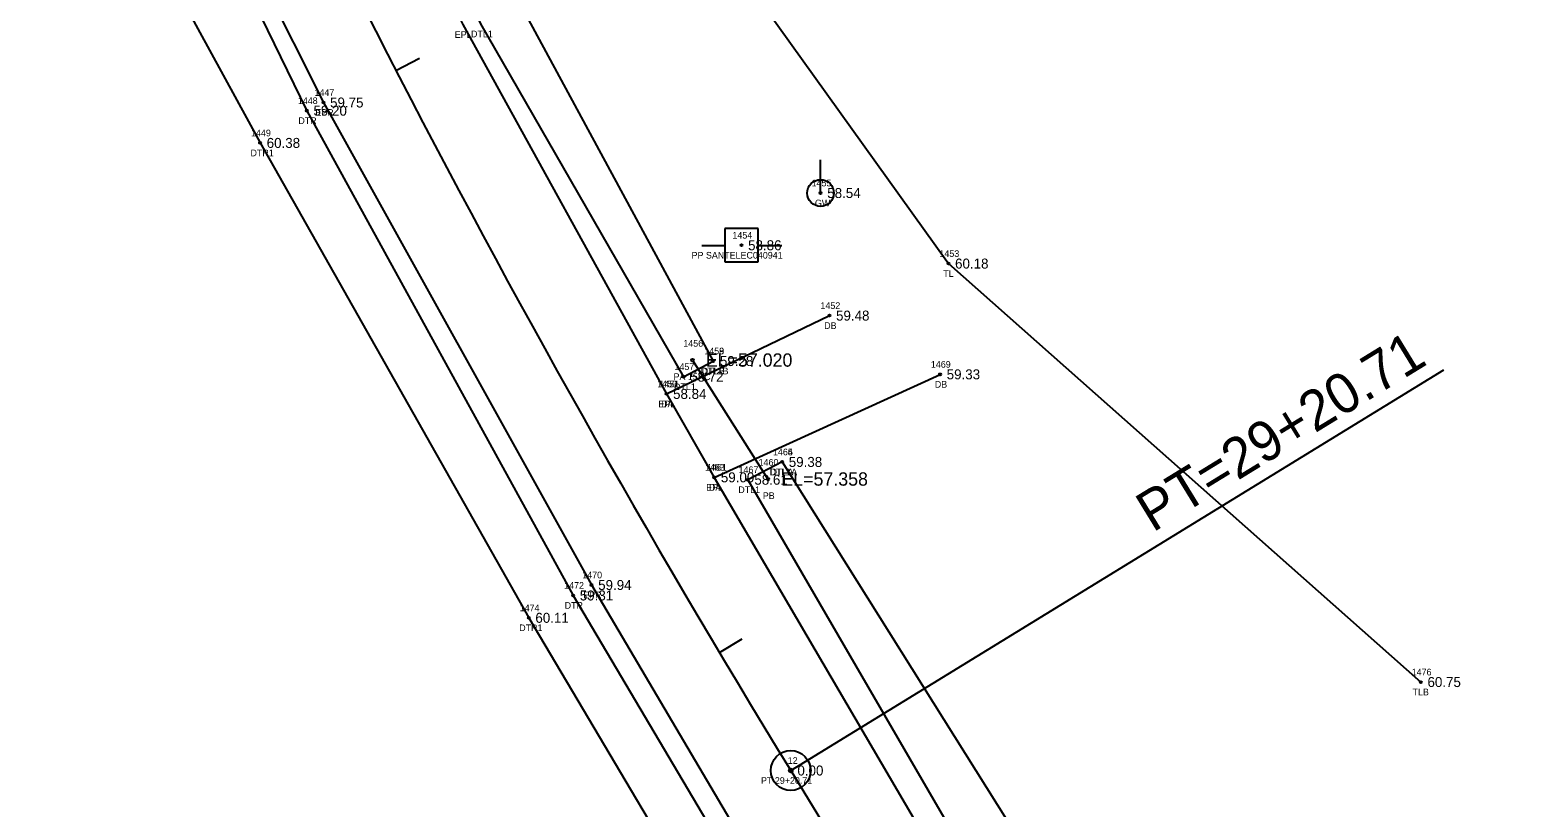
# Model space of a CAD drawing. Extents: x 2396531 to 2397633, y 770203 to 772837.
# Drawn here: x 2397143 to 2397369.4, y 770887 to 771003.7 of the extents above; entities that cross this region are included whole.
import ezdxf

# ---------------------------------------------------------------- set-up
doc = ezdxf.new("R2010")
doc.units = 0
for name, color, linetype in [('RD_EX_DR_Pipe', 7, 'Continuous'), ('RD_EX_DR_Pipe_txCode', 7, 'Continuous'), ('RD_EX_Driveway', 7, 'Continuous'), ('RD_EX_Driveway_txCode', 7, 'Continuous'), ('RD_EX_H2O', 7, 'Continuous'), ('RD_EX_H2O_txCode', 7, 'Continuous'), ('RD_EX_Road', 7, 'Continuous'), ('RD_EX_Road_txCode', 7, 'Continuous'), ('RD_EX_TX_Driveway_ELEV', 7, 'Continuous'), ('RD_EX_TX_H2O_ELEV', 7, 'Continuous'), ('RD_EX_TX_Road_ELEV', 7, 'Continuous'), ('RD_EX_TX_UT_ELEV', 7, 'Continuous'), ('RD_EX_TX_VEG_ELEV', 7, 'Continuous'), ('RD_EX_UT', 7, 'Continuous'), ('RD_EX_UT_txCode', 7, 'Continuous'), ('RD_EX_VEG', 7, 'Continuous'), ('RD_EX_VEG_txCode', 7, 'Continuous'), ('RD_HC_Cl', 7, 'Continuous'), ('RD_HC_Data', 7, 'Continuous'), ('RD_HC_Data_Tic', 7, 'Continuous'), ('RD_HC_Survey_ELEV', 7, 'Continuous'), ('RD_HC_txCode', 7, 'Continuous'), ('RD_SMD_Locator', 7, 'Continuous'), ('RD_TX_Pipe_ElevEX', 7, 'Continuous')]:
    doc.layers.add(name, color=color, linetype=linetype)

msp = doc.modelspace()

# ---------------------------------------------------------------- linework, layer by layer
at = {"layer": 'RD_EX_DR_Pipe'}
msp.add_line((2397242.45, 770954.2), (2397253.8, 770936.34), dxfattribs=at)
at = {"layer": 'RD_EX_Driveway'}
for p, q in [((2397238.54, 770949.11), (2397263.02, 770960.87)), ((2397245.72, 770936.59), (2397279.64, 770952.05))]:
    msp.add_line(p, q, dxfattribs=at)
at = {"layer": 'RD_EX_H2O'}
msp.add_line((2397255.92, 770938.9), (2397291.42, 770882.36), dxfattribs=at)
for points in [[(2397108.85, 771101.86), (2397130.27, 771108.67), (2397157.99, 771046.03), (2397184.53, 770991.63), (2397224.53, 770918.86), (2397257.48, 770863.23)], [(2397108.85, 771101.86), (2397123.52, 771093.58), (2397147.97, 771040.86), (2397177.5, 770986.79), (2397217.86, 770915.5), (2397251.15, 770859.33)], [(2397186.58, 771067.61), (2397181.36, 771063.96), (2397210.6, 771004.65), (2397241.1, 770951.7), (2397245.58, 770954.05)], [(2397186.58, 771067.61), (2397189.06, 771064.15), (2397217.13, 771006.57), (2397245.58, 770954.05)], [(2397255.92, 770938.9), (2397250.75, 770936.23), (2397284.14, 770878.8)]]:
    msp.add_lwpolyline(points, dxfattribs=at)
at = {"layer": 'RD_EX_Road'}
for points in [[(2397113.76, 771228.75), (2397130.87, 771177.98), (2397154.19, 771118.49), (2397170.38, 771081.25), (2397178.53, 771063.49), (2397207.96, 771004.56), (2397238.54, 770949.11), (2397245.72, 770936.59), (2397280.76, 770876.73)], [(2397093.16, 771212.62), (2397108.35, 771171.65), (2397122.66, 771133.29), (2397131.66, 771109.5), (2397159.86, 771046.96), (2397187.02, 770992.86), (2397227.29, 770920.43), (2397260.16, 770864.73)]]:
    msp.add_lwpolyline(points, dxfattribs=at)
at = {"layer": 'RD_EX_UT'}
for p, q in [((2397261.7, 770979.27), (2397261.7, 770984.27)), ((2397252.3, 770973.93), (2397247.3, 770973.93)), ((2397247.3, 770973.93), (2397247.3, 770968.93)), ((2397252.3, 770968.93), (2397252.3, 770973.93)), ((2397243.87, 770971.37), (2397247.33, 770971.37)), ((2397252.22, 770971.37), (2397255.87, 770971.37)), ((2397247.3, 770968.93), (2397252.3, 770968.93))]:
    msp.add_line(p, q, dxfattribs=at)
msp.add_circle((2397261.7, 770979.27), 2, dxfattribs=at)
at = {"layer": 'RD_EX_VEG'}
msp.add_lwpolyline([(2397258.88, 771057.27), (2397220.63, 771052.76), (2397280.9, 770968.68), (2397351.86, 770905.86)], dxfattribs=at)
at = {"layer": 'RD_HC_Cl'}
msp.add_line((2397257.22, 770892.58), (2397369.44, 770709.51), dxfattribs=at)
msp.add_arc((2398682.18, 771766.08), 1671.39, 194.59125, 211.50817, dxfattribs=at)
at = {"layer": 'RD_HC_Data'}
msp.add_line((2397257.22, 770892.58), (2397355.33, 770952.72), dxfattribs=at)
for radius in [3, 0.282]:
    msp.add_circle((2397257.22, 770892.58), radius, dxfattribs=at)
at = {"layer": 'RD_HC_Data_Tic'}
for p, q in [((2397197.9, 770997.67), (2397201.45, 770999.51)), ((2397246.5, 770910.3), (2397249.94, 770912.34))]:
    msp.add_line(p, q, dxfattribs=at)
at = {"layer": 'RD_SMD_Locator'}
for centre, radius in [((2397187.02, 770992.86), 0.15), ((2397184.53, 770991.63), 0.15), ((2397177.5, 770986.79), 0.15), ((2397261.7, 770979.27), 0.15), ((2397249.81, 770971.43), 0.15), ((2397280.9, 770968.68), 0.15), ((2397263.02, 770960.87), 0.15), ((2397242.45, 770954.2), 0.2), ((2397245.58, 770954.05), 0.15), ((2397245.58, 770954.05), 0.15), ((2397279.64, 770952.05), 0.15), ((2397241.1, 770951.7), 0.15), ((2397238.54, 770949.11), 0.15), ((2397238.54, 770949.11), 0.15), ((2397255.92, 770938.9), 0.15), ((2397255.92, 770938.9), 0.15), ((2397245.72, 770936.59), 0.15), ((2397245.72, 770936.59), 0.15), ((2397250.75, 770936.23), 0.15), ((2397253.8, 770936.34), 0.2), ((2397227.29, 770920.43), 0.15), ((2397224.53, 770918.86), 0.15), ((2397217.86, 770915.5), 0.15), ((2397351.86, 770905.86), 0.15), ((2397257.22, 770892.58), 0.15)]:
    msp.add_circle(centre, radius, dxfattribs=at)

# ---------------------------------------------------------------- texts
at = {"layer": 'RD_EX_DR_Pipe_txCode'}
for s, p in [('1456', (2397241.08, 770956.2)), ('PA 15RC', (2397239.61, 770951.2)), ('1460', (2397252.39, 770938.34)), ('PB', (2397253.02, 770933.34))]:
    msp.add_text(s, height=1, dxfattribs=at).set_placement(p)
at = {"layer": 'RD_EX_Driveway_txCode'}
for s, p in [('1452', (2397261.68, 770961.87)), ('DB', (2397262.24, 770958.87)), ('1469', (2397278.27, 770953.05)), ('1451', (2397237.48, 770950.11)), ('DB', (2397278.86, 770950.05)), ('DA', (2397237.75, 770947.11)), ('1463', (2397244.35, 770937.59)), ('DA', (2397244.93, 770934.59))]:
    msp.add_text(s, height=1, dxfattribs=at).set_placement(p)
at = {"layer": 'RD_EX_H2O_txCode'}
for s, p in [('DTL1', (2397209.19, 771002.65)), ('1448', (2397183.18, 770992.63)), ('DTR', (2397183.26, 770989.63)), ('1449', (2397176.15, 770987.79)), ('DTR1', (2397176.07, 770984.79)), ('1458', (2397244.23, 770955.05)), ('1459', (2397244.23, 770955.05)), ('1457', (2397239.75, 770952.7)), ('DTL1B', (2397243.7, 770952.05)), ('DTLB', (2397243.86, 770952.05)), ('DTL1', (2397239.69, 770949.7)), ('1464', (2397254.55, 770939.9)), ('1465', (2397254.55, 770939.9)), ('1467', (2397249.38, 770937.23)), ('DTL1A', (2397254.02, 770936.9)), ('DTLA', (2397254.19, 770936.9)), ('DTL1', (2397249.34, 770934.23)), ('1472', (2397223.18, 770919.86)), ('1474', (2397216.51, 770916.5)), ('DTR', (2397223.26, 770916.86)), ('DTR1', (2397216.43, 770913.5))]:
    msp.add_text(s, height=1, dxfattribs=at).set_placement(p)
at = {"layer": 'RD_EX_Road_txCode'}
for s, p in [('EPL', (2397206.75, 771002.56)), ('1447', (2397185.68, 770993.86)), ('EPR', (2397185.8, 770990.86)), ('1450', (2397237.16, 770950.11)), ('EPL', (2397237.34, 770947.11)), ('1461', (2397244.64, 770937.59)), ('EPL', (2397244.52, 770934.59)), ('1470', (2397225.9, 770921.43)), ('EPR', (2397226.06, 770918.43))]:
    msp.add_text(s, height=1, dxfattribs=at).set_placement(p)
at = {"layer": 'RD_EX_TX_Driveway_ELEV'}
for s, p in [('59.48', (2397264.02, 770960.12)), ('59.33', (2397280.64, 770951.3)), ('58.84', (2397239.54, 770948.36)), ('59.00', (2397246.72, 770935.84))]:
    msp.add_text(s, height=1.5, dxfattribs=at).set_placement(p)
at = {"layer": 'RD_EX_TX_H2O_ELEV'}
for s, p in [('59.20', (2397185.53, 770990.88)), ('60.38', (2397178.5, 770986.04)), ('59.28', (2397246.58, 770953.3)), ('59.28', (2397246.58, 770953.3)), ('58.72', (2397242.1, 770950.95)), ('59.38', (2397256.92, 770938.15)), ('59.38', (2397256.92, 770938.15)), ('58.61', (2397251.75, 770935.48)), ('59.31', (2397225.53, 770918.11)), ('60.11', (2397218.86, 770914.75))]:
    msp.add_text(s, height=1.5, dxfattribs=at).set_placement(p)
at = {"layer": 'RD_EX_TX_Road_ELEV'}
for s, p in [('59.75', (2397188.02, 770992.11)), ('58.84', (2397239.54, 770948.36)), ('59.00', (2397246.72, 770935.84)), ('59.94', (2397228.29, 770919.68))]:
    msp.add_text(s, height=1.5, dxfattribs=at).set_placement(p)
at = {"layer": 'RD_EX_TX_UT_ELEV'}
msp.add_text('58.54', height=1.5, dxfattribs=at).set_placement((2397262.7, 770978.52))
at = {"layer": 'RD_EX_TX_VEG_ELEV'}
for s, p in [('60.18', (2397281.9, 770967.93)), ('60.75', (2397352.86, 770905.11))]:
    msp.add_text(s, height=1.5, dxfattribs=at).set_placement(p)
at = {"layer": 'RD_EX_UT_txCode'}
for s, p in [('1455', (2397260.35, 770980.27)), ('GW', (2397260.85, 770977.27)), ('1454', (2397248.46, 770972.43)), ('PP SANTELEC040941', (2397242.32, 770969.43))]:
    msp.add_text(s, height=1, dxfattribs=at).set_placement(p)
at = {"layer": 'RD_EX_VEG_txCode'}
for s, p in [('1453', (2397279.55, 770969.68)), ('TL', (2397280.13, 770966.68)), ('1476', (2397350.49, 770906.86)), ('TLB', (2397350.62, 770903.86))]:
    msp.add_text(s, height=1, dxfattribs=at).set_placement(p)
at = {"layer": 'RD_HC_Data'}
msp.add_text('PT=29+20.71', height=6, rotation=31.5082, dxfattribs=at).set_placement((2397311.59, 770928.25))
at = {"layer": 'RD_HC_Survey_ELEV'}
for s, p in [('58.86', (2397250.81, 770970.68)), ('0.00', (2397258.22, 770891.83))]:
    msp.add_text(s, height=1.5, dxfattribs=at).set_placement(p)
at = {"layer": 'RD_HC_txCode'}
for s, p in [('12', (2397256.77, 770893.58)), ('PT 29+20.71', (2397252.75, 770890.58))]:
    msp.add_text(s, height=1, dxfattribs=at).set_placement(p)
at = {"layer": 'RD_TX_Pipe_ElevEX'}
for s, p in [('EL=57.020', (2397244.45, 770953.2)), ('EL=57.358', (2397255.8, 770935.34))]:
    msp.add_text(s, height=2, dxfattribs=at).set_placement(p)

doc.saveas('drawing.dxf')
